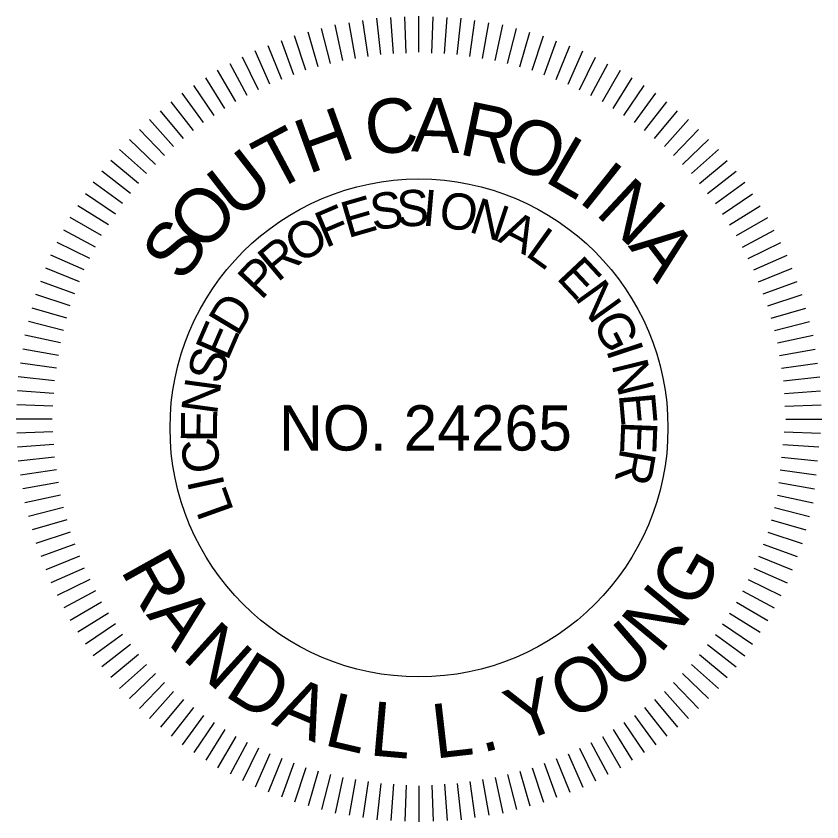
# Model space of a CAD drawing. Extents: x 1964850 to 1967424, y 1116563 to 1122204.
# Drawn here: x 1967323.1 to 1967402.3, y 1117098.9 to 1117178.1 of the extents above; entities that cross this region are included whole.
import ezdxf

# ---------------------------------------------------------------- set-up
doc = ezdxf.new("R2010")
doc.units = 0
doc.layers.add('RD_TX_PEShield', color=7, linetype='Continuous')

msp = doc.modelspace()

# ---------------------------------------------------------------- linework, layer by layer
at = {"layer": 'RD_TX_PEShield'}
for p, q in [((1967358.928, 1117174.341), (1967358.556, 1117177.881)), ((1967358.928, 1117174.341), (1967358.556, 1117177.881)), ((1967360.185, 1117174.407), (1967359.937, 1117177.954)), ((1967360.185, 1117174.407), (1967359.937, 1117177.954)), ((1967361.44, 1117174.472), (1967361.316, 1117178.026)), ((1967361.44, 1117174.472), (1967361.316, 1117178.026)), ((1967362.696, 1117174.538), (1967362.696, 1117178.098)), ((1967362.696, 1117174.538), (1967362.696, 1117178.098)), ((1967363.953, 1117174.472), (1967364.077, 1117178.026)), ((1967363.953, 1117174.472), (1967364.077, 1117178.026)), ((1967365.207, 1117174.407), (1967365.455, 1117177.954)), ((1967365.207, 1117174.407), (1967365.455, 1117177.954)), ((1967366.464, 1117174.341), (1967366.836, 1117177.881)), ((1967366.464, 1117174.341), (1967366.836, 1117177.881)), ((1967355.202, 1117173.75), (1967354.462, 1117177.233)), ((1967355.202, 1117173.75), (1967354.462, 1117177.233)), ((1967356.445, 1117173.947), (1967355.827, 1117177.449)), ((1967356.445, 1117173.947), (1967355.827, 1117177.449)), ((1967357.686, 1117174.144), (1967357.191, 1117177.665)), ((1967357.686, 1117174.144), (1967357.191, 1117177.665)), ((1967367.707, 1117174.144), (1967368.201, 1117177.665)), ((1967367.707, 1117174.144), (1967368.201, 1117177.665)), ((1967368.948, 1117173.947), (1967369.565, 1117177.449)), ((1967368.948, 1117173.947), (1967369.565, 1117177.449)), ((1967370.19, 1117173.75), (1967370.93, 1117177.233)), ((1967370.19, 1117173.75), (1967370.93, 1117177.233)), ((1967370.19, 1117173.75), (1967370.93, 1117177.233)), ((1967352.773, 1117173.1), (1967351.793, 1117176.518)), ((1967352.773, 1117173.1), (1967351.793, 1117176.518)), ((1967353.987, 1117173.425), (1967353.127, 1117176.875)), ((1967353.987, 1117173.425), (1967353.127, 1117176.875)), ((1967371.406, 1117173.425), (1967372.266, 1117176.875)), ((1967371.406, 1117173.425), (1967372.266, 1117176.875)), ((1967371.406, 1117173.425), (1967372.266, 1117176.875)), ((1967372.619, 1117173.1), (1967373.599, 1117176.518)), ((1967372.619, 1117173.1), (1967373.599, 1117176.518)), ((1967372.619, 1117173.1), (1967373.599, 1117176.518)), ((1967350.383, 1117172.323), (1967349.167, 1117175.664)), ((1967350.383, 1117172.323), (1967349.167, 1117175.664)), ((1967351.558, 1117172.774), (1967350.458, 1117176.16)), ((1967351.558, 1117172.774), (1967350.458, 1117176.16)), ((1967373.835, 1117172.774), (1967374.935, 1117176.16)), ((1967373.835, 1117172.774), (1967374.935, 1117176.16)), ((1967373.835, 1117172.774), (1967374.935, 1117176.16)), ((1967375.009, 1117172.323), (1967376.225, 1117175.664)), ((1967375.009, 1117172.323), (1967376.225, 1117175.664)), ((1967375.009, 1117172.323), (1967376.225, 1117175.664)), ((1967348.035, 1117171.422), (1967346.587, 1117174.674)), ((1967348.035, 1117171.422), (1967346.587, 1117174.674)), ((1967349.21, 1117171.873), (1967347.878, 1117175.17)), ((1967349.21, 1117171.873), (1967347.878, 1117175.17)), ((1967376.182, 1117171.873), (1967377.514, 1117175.17)), ((1967376.182, 1117171.873), (1967377.514, 1117175.17)), ((1967376.182, 1117171.873), (1967377.514, 1117175.17)), ((1967377.357, 1117171.422), (1967378.805, 1117174.674)), ((1967377.357, 1117171.422), (1967378.805, 1117174.674)), ((1967377.357, 1117171.422), (1967378.805, 1117174.674)), ((1967346.914, 1117170.851), (1967345.356, 1117174.047)), ((1967346.914, 1117170.851), (1967345.356, 1117174.047)), ((1967378.478, 1117170.851), (1967380.037, 1117174.047)), ((1967378.478, 1117170.851), (1967380.037, 1117174.047)), ((1967378.478, 1117170.851), (1967380.037, 1117174.047)), ((1967345.795, 1117170.28), (1967344.125, 1117173.42)), ((1967345.795, 1117170.28), (1967344.125, 1117173.42)), ((1967379.598, 1117170.28), (1967381.267, 1117173.42)), ((1967379.598, 1117170.28), (1967381.267, 1117173.42)), ((1967379.598, 1117170.28), (1967381.267, 1117173.42)), ((1967344.674, 1117169.709), (1967342.894, 1117172.792)), ((1967344.674, 1117169.709), (1967342.894, 1117172.792)), ((1967380.719, 1117169.709), (1967382.499, 1117172.792)), ((1967380.719, 1117169.709), (1967382.499, 1117172.792)), ((1967380.719, 1117169.709), (1967382.499, 1117172.792)), ((1967343.618, 1117169.024), (1967341.734, 1117172.039)), ((1967343.618, 1117169.024), (1967341.734, 1117172.039)), ((1967381.774, 1117169.024), (1967383.658, 1117172.039)), ((1967381.774, 1117169.024), (1967383.658, 1117172.039)), ((1967381.774, 1117169.024), (1967383.658, 1117172.039)), ((1967342.565, 1117168.339), (1967340.576, 1117171.287)), ((1967342.565, 1117168.339), (1967340.576, 1117171.287)), ((1967382.828, 1117168.339), (1967384.816, 1117171.287)), ((1967382.828, 1117168.339), (1967384.816, 1117171.287)), ((1967382.828, 1117168.339), (1967384.816, 1117171.287)), ((1967341.509, 1117167.654), (1967339.417, 1117170.534)), ((1967341.509, 1117167.654), (1967339.417, 1117170.534)), ((1967383.883, 1117167.654), (1967385.975, 1117170.534)), ((1967383.883, 1117167.654), (1967385.975, 1117170.534)), ((1967383.883, 1117167.654), (1967385.975, 1117170.534)), ((1967340.532, 1117166.862), (1967338.343, 1117169.664)), ((1967340.532, 1117166.862), (1967338.343, 1117169.664)), ((1967384.861, 1117166.862), (1967387.05, 1117169.664)), ((1967384.861, 1117166.862), (1967387.05, 1117169.664)), ((1967384.861, 1117166.862), (1967387.05, 1117169.664)), ((1967339.555, 1117166.072), (1967337.27, 1117168.795)), ((1967339.555, 1117166.072), (1967337.27, 1117168.795)), ((1967385.837, 1117166.072), (1967388.123, 1117168.795)), ((1967385.837, 1117166.072), (1967388.123, 1117168.795)), ((1967385.837, 1117166.072), (1967388.123, 1117168.795)), ((1967338.577, 1117165.28), (1967336.195, 1117167.925)), ((1967338.577, 1117165.28), (1967336.195, 1117167.925)), ((1967386.815, 1117165.28), (1967389.197, 1117167.925)), ((1967386.815, 1117165.28), (1967389.197, 1117167.925)), ((1967386.815, 1117165.28), (1967389.197, 1117167.925)), ((1967337.688, 1117164.39), (1967335.218, 1117166.948)), ((1967337.688, 1117164.39), (1967335.218, 1117166.948)), ((1967387.705, 1117164.39), (1967390.175, 1117166.948)), ((1967387.705, 1117164.39), (1967390.175, 1117166.948)), ((1967387.705, 1117164.39), (1967390.175, 1117166.948)), ((1967336.799, 1117163.502), (1967334.241, 1117165.972)), ((1967336.799, 1117163.502), (1967334.241, 1117165.972)), ((1967388.593, 1117163.502), (1967391.151, 1117165.972)), ((1967388.593, 1117163.502), (1967391.151, 1117165.972)), ((1967388.593, 1117163.502), (1967391.151, 1117165.972)), ((1967335.909, 1117162.612), (1967333.264, 1117164.994)), ((1967335.909, 1117162.612), (1967333.264, 1117164.994)), ((1967389.483, 1117162.612), (1967392.128, 1117164.994)), ((1967389.483, 1117162.612), (1967392.128, 1117164.994)), ((1967389.483, 1117162.612), (1967392.128, 1117164.994)), ((1967335.118, 1117161.634), (1967332.394, 1117163.92)), ((1967335.118, 1117161.634), (1967332.394, 1117163.92)), ((1967390.275, 1117161.634), (1967392.998, 1117163.92)), ((1967390.275, 1117161.634), (1967392.998, 1117163.92)), ((1967390.275, 1117161.634), (1967392.998, 1117163.92)), ((1967334.327, 1117160.658), (1967331.525, 1117162.847)), ((1967334.327, 1117160.658), (1967331.525, 1117162.847)), ((1967391.065, 1117160.658), (1967393.867, 1117162.847)), ((1967391.065, 1117160.658), (1967393.867, 1117162.847)), ((1967391.065, 1117160.658), (1967393.867, 1117162.847)), ((1967333.535, 1117159.68), (1967330.655, 1117161.772)), ((1967333.535, 1117159.68), (1967330.655, 1117161.772)), ((1967391.857, 1117159.68), (1967394.737, 1117161.772)), ((1967391.857, 1117159.68), (1967394.737, 1117161.772)), ((1967391.857, 1117159.68), (1967394.737, 1117161.772)), ((1967332.85, 1117158.625), (1967329.902, 1117160.613)), ((1967332.85, 1117158.625), (1967329.902, 1117160.613)), ((1967392.542, 1117158.625), (1967395.49, 1117160.613)), ((1967392.542, 1117158.625), (1967395.49, 1117160.613)), ((1967392.542, 1117158.625), (1967395.49, 1117160.613)), ((1967332.165, 1117157.571), (1967329.15, 1117159.455)), ((1967332.165, 1117157.571), (1967329.15, 1117159.455)), ((1967393.227, 1117157.571), (1967396.242, 1117159.455)), ((1967393.227, 1117157.571), (1967396.242, 1117159.455)), ((1967393.227, 1117157.571), (1967396.242, 1117159.455)), ((1967331.48, 1117156.516), (1967328.397, 1117158.296)), ((1967331.48, 1117156.516), (1967328.397, 1117158.296)), ((1967393.912, 1117156.516), (1967396.995, 1117158.296)), ((1967393.912, 1117156.516), (1967396.995, 1117158.296)), ((1967393.912, 1117156.516), (1967396.995, 1117158.296)), ((1967330.909, 1117155.395), (1967327.77, 1117157.064)), ((1967330.909, 1117155.395), (1967327.77, 1117157.064)), ((1967394.483, 1117155.395), (1967397.623, 1117157.064)), ((1967394.483, 1117155.395), (1967397.623, 1117157.064)), ((1967394.483, 1117155.395), (1967397.623, 1117157.064)), ((1967330.339, 1117154.275), (1967327.143, 1117155.834)), ((1967330.339, 1117154.275), (1967327.143, 1117155.834)), ((1967395.054, 1117154.275), (1967398.25, 1117155.834)), ((1967395.054, 1117154.275), (1967398.25, 1117155.834)), ((1967395.054, 1117154.275), (1967398.25, 1117155.834)), ((1967329.767, 1117153.154), (1967326.515, 1117154.602)), ((1967329.767, 1117153.154), (1967326.515, 1117154.602)), ((1967395.625, 1117153.154), (1967398.877, 1117154.602)), ((1967395.625, 1117153.154), (1967398.877, 1117154.602)), ((1967395.625, 1117153.154), (1967398.877, 1117154.602)), ((1967329.317, 1117151.979), (1967326.02, 1117153.311)), ((1967329.317, 1117151.979), (1967326.02, 1117153.311)), ((1967396.076, 1117151.979), (1967399.373, 1117153.311)), ((1967396.076, 1117151.979), (1967399.373, 1117153.311)), ((1967396.076, 1117151.979), (1967399.373, 1117153.311)), ((1967328.866, 1117150.806), (1967325.525, 1117152.022)), ((1967328.866, 1117150.806), (1967325.525, 1117152.022)), ((1967396.526, 1117150.806), (1967399.867, 1117152.022)), ((1967396.526, 1117150.806), (1967399.867, 1117152.022)), ((1967396.526, 1117150.806), (1967399.867, 1117152.022)), ((1967328.415, 1117149.632), (1967325.03, 1117150.732)), ((1967328.415, 1117149.632), (1967325.03, 1117150.732)), ((1967396.977, 1117149.632), (1967400.363, 1117150.732)), ((1967396.977, 1117149.632), (1967400.363, 1117150.732)), ((1967396.977, 1117149.632), (1967400.363, 1117150.732)), ((1967328.09, 1117148.416), (1967324.672, 1117149.396)), ((1967328.09, 1117148.416), (1967324.672, 1117149.396)), ((1967397.303, 1117148.416), (1967400.721, 1117149.396)), ((1967397.303, 1117148.416), (1967400.721, 1117149.396)), ((1967397.303, 1117148.416), (1967400.721, 1117149.396)), ((1967327.764, 1117147.203), (1967324.314, 1117148.063)), ((1967327.764, 1117147.203), (1967324.314, 1117148.063)), ((1967397.628, 1117147.203), (1967401.078, 1117148.063)), ((1967397.628, 1117147.203), (1967401.078, 1117148.063)), ((1967397.628, 1117147.203), (1967401.078, 1117148.063)), ((1967327.439, 1117145.987), (1967323.957, 1117146.727)), ((1967327.439, 1117145.987), (1967323.957, 1117146.727)), ((1967397.953, 1117145.987), (1967401.436, 1117146.727)), ((1967397.953, 1117145.987), (1967401.436, 1117146.727)), ((1967397.953, 1117145.987), (1967401.436, 1117146.727)), ((1967327.242, 1117144.745), (1967323.74, 1117145.362)), ((1967327.242, 1117144.745), (1967323.74, 1117145.362)), ((1967398.15, 1117144.745), (1967401.652, 1117145.362)), ((1967398.15, 1117144.745), (1967401.652, 1117145.362)), ((1967398.15, 1117144.745), (1967401.652, 1117145.362)), ((1967327.045, 1117143.504), (1967323.524, 1117143.998)), ((1967327.045, 1117143.504), (1967323.524, 1117143.998)), ((1967398.347, 1117143.504), (1967401.868, 1117143.998)), ((1967398.347, 1117143.504), (1967401.868, 1117143.998)), ((1967398.347, 1117143.504), (1967401.868, 1117143.998)), ((1967326.849, 1117142.261), (1967323.308, 1117142.633)), ((1967326.849, 1117142.261), (1967323.308, 1117142.633)), ((1967398.544, 1117142.261), (1967402.084, 1117142.633)), ((1967398.544, 1117142.261), (1967402.084, 1117142.633)), ((1967398.544, 1117142.261), (1967402.084, 1117142.633)), ((1967326.783, 1117141.004), (1967323.236, 1117141.252)), ((1967326.783, 1117141.004), (1967323.236, 1117141.252)), ((1967398.61, 1117141.004), (1967402.157, 1117141.252)), ((1967398.61, 1117141.004), (1967402.157, 1117141.252)), ((1967398.61, 1117141.004), (1967402.157, 1117141.252)), ((1967326.717, 1117139.75), (1967323.163, 1117139.874)), ((1967326.717, 1117139.75), (1967323.163, 1117139.874)), ((1967398.675, 1117139.75), (1967402.229, 1117139.874)), ((1967398.675, 1117139.75), (1967402.229, 1117139.874)), ((1967398.675, 1117139.75), (1967402.229, 1117139.874)), ((1967326.651, 1117138.493), (1967323.091, 1117138.493)), ((1967326.651, 1117138.493), (1967323.091, 1117138.493)), ((1967398.741, 1117138.493), (1967402.301, 1117138.493)), ((1967398.741, 1117138.493), (1967402.301, 1117138.493)), ((1967398.741, 1117138.493), (1967402.301, 1117138.493)), ((1967326.717, 1117137.237), (1967323.163, 1117137.113)), ((1967326.717, 1117137.237), (1967323.163, 1117137.113)), ((1967398.609, 1117137.239), (1967402.156, 1117137.115)), ((1967398.609, 1117137.239), (1967402.156, 1117137.115)), ((1967326.783, 1117135.982), (1967323.236, 1117135.734)), ((1967326.783, 1117135.982), (1967323.236, 1117135.734)), ((1967398.478, 1117135.991), (1967402.012, 1117135.744)), ((1967398.478, 1117135.991), (1967402.012, 1117135.744)), ((1967326.849, 1117134.725), (1967323.308, 1117134.353)), ((1967326.849, 1117134.725), (1967323.308, 1117134.353)), ((1967398.347, 1117134.746), (1967401.868, 1117134.376)), ((1967398.347, 1117134.746), (1967401.868, 1117134.376)), ((1967327.045, 1117133.483), (1967323.524, 1117132.988)), ((1967327.045, 1117133.483), (1967323.524, 1117132.988)), ((1967398.216, 1117133.501), (1967401.725, 1117133.008)), ((1967398.216, 1117133.501), (1967401.725, 1117133.008)), ((1967327.242, 1117132.242), (1967323.74, 1117131.624)), ((1967327.242, 1117132.242), (1967323.74, 1117131.624)), ((1967398.085, 1117132.253), (1967401.581, 1117131.637)), ((1967398.085, 1117132.253), (1967401.581, 1117131.637)), ((1967327.439, 1117130.999), (1967323.957, 1117130.259)), ((1967327.439, 1117130.999), (1967323.957, 1117130.259)), ((1967397.953, 1117130.999), (1967401.436, 1117130.259)), ((1967397.953, 1117130.999), (1967401.436, 1117130.259)), ((1967327.764, 1117129.784), (1967324.314, 1117128.923)), ((1967327.764, 1117129.784), (1967324.314, 1117128.923)), ((1967397.628, 1117129.784), (1967401.078, 1117128.923)), ((1967397.628, 1117129.784), (1967401.078, 1117128.923)), ((1967328.09, 1117128.57), (1967324.672, 1117127.59)), ((1967328.09, 1117128.57), (1967324.672, 1117127.59)), ((1967397.303, 1117128.57), (1967400.721, 1117127.59)), ((1967397.303, 1117128.57), (1967400.721, 1117127.59)), ((1967328.415, 1117127.355), (1967325.03, 1117126.255)), ((1967396.977, 1117127.355), (1967400.363, 1117126.255)), ((1967396.977, 1117127.355), (1967400.363, 1117126.255)), ((1967328.866, 1117126.18), (1967325.525, 1117124.964)), ((1967328.866, 1117126.18), (1967325.525, 1117124.964)), ((1967396.526, 1117126.18), (1967399.867, 1117124.964)), ((1967396.526, 1117126.18), (1967399.867, 1117124.964)), ((1967329.317, 1117125.007), (1967326.02, 1117123.675)), ((1967329.317, 1117125.007), (1967326.02, 1117123.675)), ((1967396.076, 1117125.007), (1967399.373, 1117123.675)), ((1967396.076, 1117125.007), (1967399.373, 1117123.675)), ((1967329.767, 1117123.832), (1967326.515, 1117122.384)), ((1967329.767, 1117123.832), (1967326.515, 1117122.384)), ((1967395.625, 1117123.832), (1967398.877, 1117122.384)), ((1967395.625, 1117123.832), (1967398.877, 1117122.384)), ((1967330.339, 1117122.711), (1967327.143, 1117121.153)), ((1967330.339, 1117122.711), (1967327.143, 1117121.153)), ((1967395.054, 1117122.711), (1967398.25, 1117121.153)), ((1967395.054, 1117122.711), (1967398.25, 1117121.153)), ((1967330.909, 1117121.592), (1967327.77, 1117119.922)), ((1967330.909, 1117121.592), (1967327.77, 1117119.922)), ((1967394.483, 1117121.592), (1967397.623, 1117119.922)), ((1967394.483, 1117121.592), (1967397.623, 1117119.922)), ((1967331.48, 1117120.471), (1967328.397, 1117118.691)), ((1967331.48, 1117120.471), (1967328.397, 1117118.691)), ((1967393.912, 1117120.471), (1967396.995, 1117118.691)), ((1967393.912, 1117120.471), (1967396.995, 1117118.691)), ((1967332.165, 1117119.415), (1967329.15, 1117117.531)), ((1967332.165, 1117119.415), (1967329.15, 1117117.531)), ((1967393.227, 1117119.415), (1967396.242, 1117117.531)), ((1967393.227, 1117119.415), (1967396.242, 1117117.531)), ((1967332.85, 1117118.362), (1967329.902, 1117116.373)), ((1967332.85, 1117118.362), (1967329.902, 1117116.373)), ((1967392.542, 1117118.362), (1967395.49, 1117116.373)), ((1967392.542, 1117118.362), (1967395.49, 1117116.373)), ((1967333.535, 1117117.306), (1967330.655, 1117115.214)), ((1967333.535, 1117117.306), (1967330.655, 1117115.214)), ((1967391.857, 1117117.306), (1967394.737, 1117115.214)), ((1967391.857, 1117117.306), (1967394.737, 1117115.214)), ((1967334.327, 1117116.329), (1967331.525, 1117114.14)), ((1967334.327, 1117116.329), (1967331.525, 1117114.14)), ((1967391.065, 1117116.329), (1967393.867, 1117114.14)), ((1967391.065, 1117116.329), (1967393.867, 1117114.14)), ((1967335.118, 1117115.352), (1967332.394, 1117113.067)), ((1967335.118, 1117115.352), (1967332.394, 1117113.067)), ((1967390.275, 1117115.352), (1967392.998, 1117113.067)), ((1967390.275, 1117115.352), (1967392.998, 1117113.067)), ((1967335.909, 1117114.374), (1967333.264, 1117111.992)), ((1967335.909, 1117114.374), (1967333.264, 1117111.992)), ((1967389.483, 1117114.374), (1967392.128, 1117111.992)), ((1967389.483, 1117114.374), (1967392.128, 1117111.992)), ((1967336.799, 1117113.485), (1967334.241, 1117111.015)), ((1967336.799, 1117113.485), (1967334.241, 1117111.015)), ((1967388.593, 1117113.485), (1967391.151, 1117111.015)), ((1967388.593, 1117113.485), (1967391.151, 1117111.015)), ((1967337.688, 1117112.596), (1967335.218, 1117110.038)), ((1967337.688, 1117112.596), (1967335.218, 1117110.038)), ((1967387.705, 1117112.596), (1967390.175, 1117110.038)), ((1967387.705, 1117112.596), (1967390.175, 1117110.038)), ((1967338.577, 1117111.706), (1967336.195, 1117109.061)), ((1967338.577, 1117111.706), (1967336.195, 1117109.061)), ((1967386.815, 1117111.706), (1967389.197, 1117109.061)), ((1967339.555, 1117110.915), (1967337.27, 1117108.191)), ((1967339.555, 1117110.915), (1967337.27, 1117108.191)), ((1967385.837, 1117110.915), (1967388.123, 1117108.191)), ((1967385.837, 1117110.915), (1967388.123, 1117108.191)), ((1967340.532, 1117110.124), (1967338.343, 1117107.322)), ((1967340.532, 1117110.124), (1967338.343, 1117107.322)), ((1967384.861, 1117110.124), (1967387.05, 1117107.322)), ((1967384.861, 1117110.124), (1967387.05, 1117107.322)), ((1967341.509, 1117109.332), (1967339.417, 1117106.452)), ((1967341.509, 1117109.332), (1967339.417, 1117106.452)), ((1967383.883, 1117109.332), (1967385.975, 1117106.452)), ((1967383.883, 1117109.332), (1967385.975, 1117106.452)), ((1967342.565, 1117108.647), (1967340.576, 1117105.699)), ((1967342.565, 1117108.647), (1967340.576, 1117105.699)), ((1967382.828, 1117108.647), (1967384.816, 1117105.699)), ((1967382.828, 1117108.647), (1967384.816, 1117105.699)), ((1967343.618, 1117107.962), (1967341.734, 1117104.947)), ((1967343.618, 1117107.962), (1967341.734, 1117104.947)), ((1967381.774, 1117107.962), (1967383.658, 1117104.947)), ((1967381.774, 1117107.962), (1967383.658, 1117104.947)), ((1967344.674, 1117107.277), (1967342.894, 1117104.194)), ((1967344.674, 1117107.277), (1967342.894, 1117104.194)), ((1967345.795, 1117106.706), (1967344.125, 1117103.567)), ((1967345.795, 1117106.706), (1967344.125, 1117103.567)), ((1967379.598, 1117106.706), (1967381.267, 1117103.567)), ((1967379.598, 1117106.706), (1967381.267, 1117103.567)), ((1967380.719, 1117107.277), (1967382.499, 1117104.194)), ((1967380.719, 1117107.277), (1967382.499, 1117104.194)), ((1967346.914, 1117106.136), (1967345.356, 1117102.94)), ((1967346.914, 1117106.136), (1967345.356, 1117102.94)), ((1967378.478, 1117106.136), (1967380.037, 1117102.94)), ((1967378.478, 1117106.136), (1967380.037, 1117102.94)), ((1967348.035, 1117105.564), (1967346.587, 1117102.312)), ((1967348.035, 1117105.564), (1967346.587, 1117102.312)), ((1967349.21, 1117105.114), (1967347.878, 1117101.817)), ((1967349.21, 1117105.114), (1967347.878, 1117101.817)), ((1967376.182, 1117105.114), (1967377.514, 1117101.817)), ((1967376.182, 1117105.114), (1967377.514, 1117101.817)), ((1967377.357, 1117105.564), (1967378.805, 1117102.312)), ((1967377.357, 1117105.564), (1967378.805, 1117102.312)), ((1967350.383, 1117104.663), (1967349.167, 1117101.322)), ((1967350.383, 1117104.663), (1967349.167, 1117101.322)), ((1967351.558, 1117104.212), (1967350.458, 1117100.827)), ((1967351.558, 1117104.212), (1967350.458, 1117100.827)), ((1967373.835, 1117104.212), (1967374.935, 1117100.827)), ((1967373.835, 1117104.212), (1967374.935, 1117100.827)), ((1967375.009, 1117104.663), (1967376.225, 1117101.322)), ((1967375.009, 1117104.663), (1967376.225, 1117101.322)), ((1967352.773, 1117103.887), (1967351.793, 1117100.469)), ((1967352.773, 1117103.887), (1967351.793, 1117100.469)), ((1967353.987, 1117103.561), (1967353.127, 1117100.111)), ((1967353.987, 1117103.561), (1967353.127, 1117100.111)), ((1967371.406, 1117103.561), (1967372.266, 1117100.111)), ((1967371.406, 1117103.561), (1967372.266, 1117100.111)), ((1967372.619, 1117103.887), (1967373.599, 1117100.469)), ((1967372.619, 1117103.887), (1967373.599, 1117100.469)), ((1967355.202, 1117103.236), (1967354.462, 1117099.754)), ((1967355.202, 1117103.236), (1967354.462, 1117099.754)), ((1967356.445, 1117103.039), (1967355.827, 1117099.537)), ((1967356.445, 1117103.039), (1967355.827, 1117099.537)), ((1967357.686, 1117102.842), (1967357.191, 1117099.321)), ((1967357.686, 1117102.842), (1967357.191, 1117099.321)), ((1967358.928, 1117102.646), (1967358.556, 1117099.105)), ((1967358.928, 1117102.646), (1967358.556, 1117099.105)), ((1967366.464, 1117102.646), (1967366.836, 1117099.105)), ((1967366.464, 1117102.646), (1967366.836, 1117099.105)), ((1967367.707, 1117102.842), (1967368.201, 1117099.321)), ((1967367.707, 1117102.842), (1967368.201, 1117099.321)), ((1967368.948, 1117103.039), (1967369.565, 1117099.537)), ((1967368.948, 1117103.039), (1967369.565, 1117099.537)), ((1967370.19, 1117103.236), (1967370.93, 1117099.754)), ((1967370.19, 1117103.236), (1967370.93, 1117099.754)), ((1967360.185, 1117102.58), (1967359.937, 1117099.033)), ((1967360.185, 1117102.58), (1967359.937, 1117099.033)), ((1967361.44, 1117102.514), (1967361.316, 1117098.96)), ((1967361.44, 1117102.514), (1967361.316, 1117098.96)), ((1967362.696, 1117102.448), (1967362.696, 1117098.888)), ((1967362.696, 1117102.448), (1967362.696, 1117098.888)), ((1967363.953, 1117102.514), (1967364.077, 1117098.96)), ((1967363.953, 1117102.514), (1967364.077, 1117098.96)), ((1967365.207, 1117102.58), (1967365.455, 1117099.033)), ((1967365.207, 1117102.58), (1967365.455, 1117099.033))]:
    msp.add_line(p, q, dxfattribs=at)
msp.add_circle((1967362.696, 1117137.615), 24.475, dxfattribs=at)

# ---------------------------------------------------------------- texts
for s, height, rotation, p in [('C', 5.34, 6.88322, (1967357.69, 1117164.353)), ('A', 5.34, 357.94482, (1967361.905, 1117164.806)), ('R', 5.34, 348.26699, (1967366.488, 1117164.552)), ('H', 5.34, 19.91024, (1967351.792, 1117162.536)), ('O', 5.34, 339.32858, (1967370.627, 1117163.636)), ('T', 5.34, 28.09472, (1967348.355, 1117160.73)), ('L', 5.34, 329.65075, (1967374.888, 1117161.932)), ('U', 5.34, 37.77255, (1967344.674, 1117157.99)), ('I', 5.34, 321.46627, (1967378.226, 1117159.949)), ('N', 5.34, 317.00069, (1967379.918, 1117158.672)), ('O', 5.34, 47.45038, (1967341.505, 1117154.671)), ('E', 3.56, 16.18428, (1967355.694, 1117156.249)), ('S', 3.56, 8.69092, (1967358.184, 1117157.003)), ('S', 3.56, 1.78995, (1967360.546, 1117157.405)), ('I', 3.56, 354.88899, (1967362.94, 1117157.52)), ('O', 3.56, 350.40454, (1967364.495, 1117157.44)), ('N', 3.56, 341.70291, (1967367.474, 1117156.939)), ('F', 3.56, 23.08525, (1967353.506, 1117155.273)), ('A', 3.56, 333.00129, (1967370.342, 1117155.994)), ('S', 5.34, 54.90268, (1967339.472, 1117151.778)), ('O', 3.56, 31.78688, (1967350.94, 1117153.679)), ('L', 3.56, 324.29966, (1967373.035, 1117154.626)), ('A', 5.34, 307.32286, (1967383.212, 1117155.477)), ('R', 3.56, 39.89024, (1967348.793, 1117151.862)), ('P', 3.56, 46.7912, (1967347.182, 1117150.088)), ('E', 3.56, 313.22511, (1967376.11, 1117152.323)), ('N', 3.56, 305.73175, (1967377.913, 1117150.448)), ('D', 3.56, 59.07401, (1967344.884, 1117146.502)), ('G', 3.56, 297.03012, (1967379.68, 1117147.998)), ('E', 3.56, 66.56738, (1967343.877, 1117144.103)), ('S', 3.56, 73.46834, (1967343.234, 1117141.795)), ('I', 3.56, 288.3285, (1967381.055, 1117145.309)), ('N', 3.56, 283.84405, (1967381.6, 1117143.85)), ('N', 3.56, 82.16997, (1967342.826, 1117138.803)), ('E', 3.56, 275.14243, (1967382.326, 1117140.918)), ('E', 3.56, 89.66334, (1967342.84, 1117136.201)), ('E', 3.56, 267.64906, (1967382.589, 1117138.33)), ('C', 3.56, 97.7667, (1967343.238, 1117133.416)), ('R', 3.56, 260.15569, (1967382.513, 1117135.73)), ('I', 3.56, 102.25114, (1967343.626, 1117131.908)), ('L', 3.56, 109.74451, (1967344.533, 1117129.47)), ('R', 5.34, 299.14926, (1967333.294, 1117123.641)), ('G', 5.34, 60.11131, (1967389.805, 1117119.591)), ('N', 5.34, 50.43348, (1967386.39, 1117115.291)), ('A', 5.34, 308.08766, (1967335.822, 1117119.243)), ('N', 5.34, 317.7655, (1967339.293, 1117114.986)), ('U', 5.34, 40.75564, (1967382.3, 1117111.625)), ('D', 5.34, 327.44333, (1967343.43, 1117111.374)), ('O', 5.34, 31.07781, (1967377.651, 1117108.7)), ('Y', 5.34, 21.39998, (1967372.578, 1117106.597)), ('A', 5.34, 337.12116, (1967348.116, 1117108.509)), ('L', 5.34, 346.799, (1967353.216, 1117106.472)), ('L', 5.34, 354.98347, (1967357.746, 1117105.44)), ('L', 5.34, 6.51713, (1967364.279, 1117105.1)), ('.', 5.34, 14.70161, (1967368.892, 1117105.656))]:
    msp.add_text(s, height=height, rotation=rotation, dxfattribs=at).set_placement(p)
msp.add_text('NO. 24265', height=4.4501, dxfattribs=at).set_placement((1967348.942, 1117135.39))

doc.saveas('drawing.dxf')
